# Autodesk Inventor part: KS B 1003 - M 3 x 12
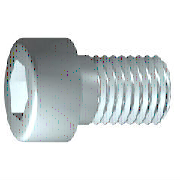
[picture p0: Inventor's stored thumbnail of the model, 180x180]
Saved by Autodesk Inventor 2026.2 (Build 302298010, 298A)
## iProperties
Created: 2025-01
Part Number: KS B 1003 - M 3 x 12
Material: 강철, 연강
Description: 6각머리 태핑 나사
Document SubType Name: Modeling
Standard: KS B 1003
Designer: work
Standards Organization: KS
Language: ko-KR
Size Designation: M 3 x 12
Categories: <MemberInstance><Categories><Category DisplayName="조임쇠" InternalName="e4da775c-781d-43d5-af7c-5136215cf5a6" Mnemonic="FSTN"><Category DisplayName="볼트" InternalN
Density: 7.85 g/cm^3
Appearance: 반연마
IsCustomPart: 1
Author: work
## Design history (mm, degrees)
workplane "Work Plane1"
fillet "Fillet2" dims "d30" = 0.1 (= R)
revolve "본체" stored, may be unused: angle "d10" = 90 deg
sketch "스케치2"
  geometry: L1 (0, -3.85)-(0, 3.85) reference; L2 (-3.85, 0)-(3.85, 0) reference; L3 (1.443, 0)-(0.722, -1.25); L4 (0.722, -1.25)-(-0.722, -1.25); L5 (-0.722, -1.25)-(-1.443, 0); L6 (-1.443, 0)-(-0.722, 1.25); L7 (-0.722, 1.25)-(0.722, 1.25); L8 (0.722, 1.25)-(1.443, 0); 2 further points
  constraints: 12 end point, 1 coincident, 1 horizontal alignment, 1 point on line, 12 other
extrude "슬롯" join sketch "스케치2" stored distance "d11" = 10; taper "d12" = 0 deg
body "Solid1"
fillet "모깎기1" dims "d17" = 0.3 (= RR)
feature "스레드" dims "d13" = 10.75 (= GEL), "d14" = 0
chamfer "모따기1" distance "d15" = 0.30673 (= -0.5 x SPD + 0.5 x GD); stored, may be unused: second distance "d16" = 0.30673 (= GUL), angle "d27" = 45 deg
sketch "스케치1"
  geometry: L1 (-0.867, 0)-(12, 0); L2 (12, 0)-(12, 1.5); L3 (12, 1.5)-(1.25, 1.5); L4 (1.25, 1.5)-(0.943, 1.5); L5 (0.943, 1.5)-(0, 1.5); L6 (0, 1.5)-(0, 2.75); L7 (0, 2.75)-(-3, 2.75); L8 (-3, 2.75)-(-3, 1.443); L9 (-3, 1.443)-(-1.7, 1.443); L10 (-1.7, 1.443)-(-0.867, 0); L11 (-6, 0)-(15, 0) reference; L12 (0, -0.55)-(0, 3.3) reference; L13 (1.25, 1.5)-(0, 1.5)
  constraints: 22 end point, 6 parallel, 2 collinear, 2 perpendicular, 1 horizontal, 1 point on line
  dimensions: "d1" = 10.75 distance from line of L3.end L2 (= GEL); "d2" = 0.30683 distance of L4.end L3.end (computed from GAL); "d3" = 3 distance between parallel lines of L8 L6 (= KOH); "d4" = 1.3 distance of L8.end L9.end (= INTI); "d5" = 60 deg angle of L10 L1; "d6" = 3 diameter of L3 L1 (= GD); "d7" = 3 diameter of L5 L1 (= BDM); "d8" = 2.88675 diameter of L9 L1 (= 1.1547 x SW); "d9" = 5.5 diameter of L7 L1 (= KOD); "d26" = 12 distance between parallel lines of L12 L2 (= NLG)
other parameters: "GD" = 3 (= NND) [user parameter; used in 2 equation terms], "NLG" = 12 [user parameter; used in 1 equation term], "GEL" = 10.75 [user parameter; used in 2 equation terms], "KOD" = 5.5 [user parameter; used in 1 equation term], "KOH" = 3 [user parameter; used in 1 equation term], "INTI" = 1.3 [user parameter; used in 1 equation term], "GAL" = 0.30673 (= 0.61345 x PTC) [user parameter; used in 1 equation term], "GUL" = 0.30673 (= 0.61345 x PTC) [user parameter; used in 1 equation term], "BDM" = 3 (= NND) [user parameter; used in 1 equation term], "SW" = 2.5 [user parameter; used in 2 equation terms], "RR" = 0.3 [user parameter; used in 1 equation term], "SPD" = 2.38655 (= NND - 1.2269 x PTC) [user parameter; used in 1 equation term], "d19" = 0, "d28" = 0, "d29" = 0, "R" = 0.1 [user parameter; used in 1 equation term], "PHH" = 0.1 [user parameter], "GD1" = 2.38655 (= THREADDIA - 1.2269 x PTC) [user parameter], "THREADDIA" = 3 [user parameter; used in 1 equation term], "FAWI" = 45 deg [user parameter], "PTC" = 0.5 [user parameter; used in 5 equation terms], "NND" = 3 [user parameter; used in 3 equation terms], "TOA" = 30 deg [user parameter], "E0" = 2.8875 (= 1.155 x SW) [user parameter]
